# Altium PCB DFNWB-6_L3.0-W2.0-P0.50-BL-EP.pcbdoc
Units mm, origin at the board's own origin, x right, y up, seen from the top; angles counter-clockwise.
Board outline 14.9 x 16.22 mm, 2 copper layers (Top Layer, Bottom Layer), stack 0 mm thick; 1 components, 0 nets, 7 pads, 0 vias.
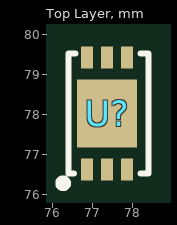
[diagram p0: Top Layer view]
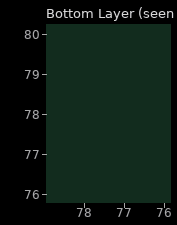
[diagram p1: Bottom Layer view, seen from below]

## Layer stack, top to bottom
Top Layer: signal copper (thickness not stored)
Bottom Layer: signal copper (thickness not stored)

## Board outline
84.75,69.85 69.85,69.85 69.85,86.065 84.75,86.065

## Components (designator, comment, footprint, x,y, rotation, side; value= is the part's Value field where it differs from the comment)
U? "" DFNWB-6_L3.0-W2.0-P0.50-BL-EP 77.37,78.04 r0 top

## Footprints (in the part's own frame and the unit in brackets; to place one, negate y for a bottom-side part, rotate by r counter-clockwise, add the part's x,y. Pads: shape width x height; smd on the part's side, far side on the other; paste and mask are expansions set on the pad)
DFNWB-6_L3.0-W2.0-P0.50-BL-EP [mm]
  rect 0.3x0.55 smd: 1(-0.5,-1.4) 2(0,-1.4) 3(0.5,-1.4) 4(0.5,1.4) 5(0,1.4) 6(-0.5,1.4)
  rect 1.5x1.7 smd: 7(0,0)
  silkscreen extent -1.17,-1.82 1.03,1.5

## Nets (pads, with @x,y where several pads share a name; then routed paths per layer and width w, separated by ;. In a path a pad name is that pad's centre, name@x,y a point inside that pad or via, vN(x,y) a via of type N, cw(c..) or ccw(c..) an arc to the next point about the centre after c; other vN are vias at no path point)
pads on no net: U?.1 U?.2 U?.3 U?.4 U?.5 U?.6 U?.7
